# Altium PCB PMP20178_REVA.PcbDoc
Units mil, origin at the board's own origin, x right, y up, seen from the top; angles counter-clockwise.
Board outline 3000 x 2000 mil, 4 copper layers (Top Layer, Mid-Layer 1, Mid-Layer 2, Bottom Layer), stack 61.2 mil thick; 78 components, 25 nets, 160 pads, 125 vias.
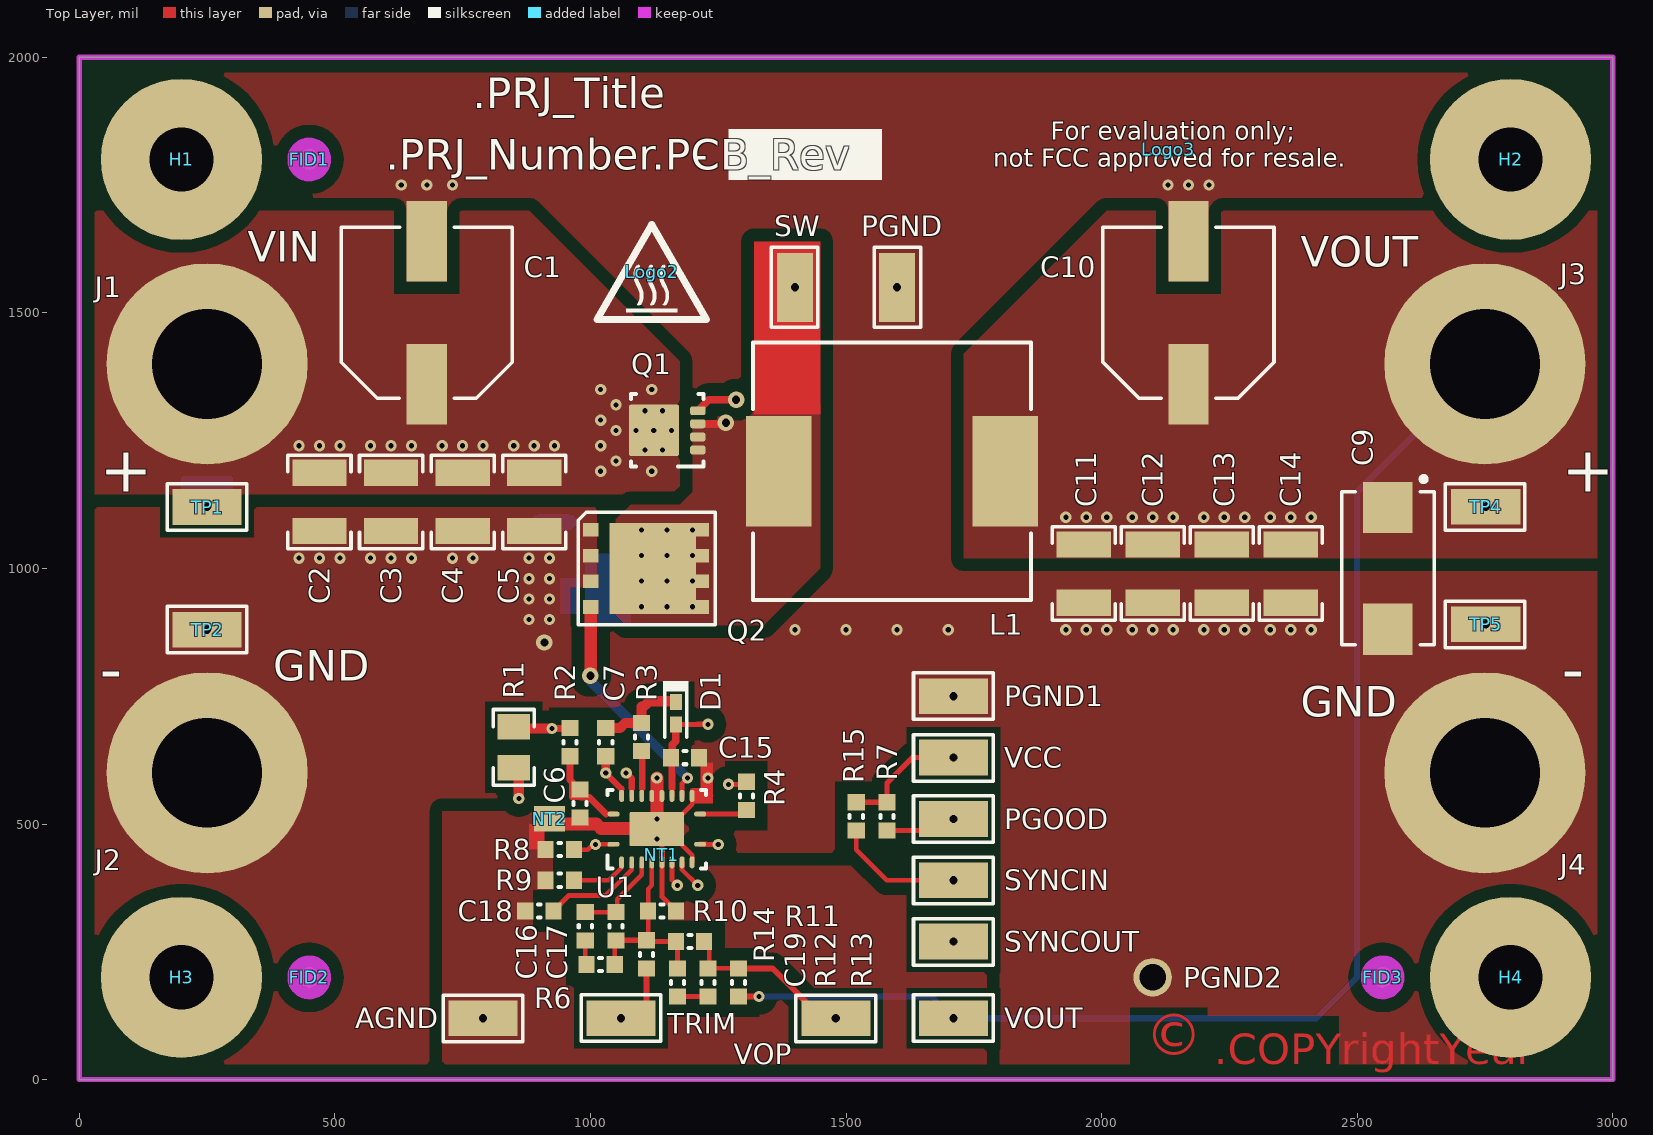
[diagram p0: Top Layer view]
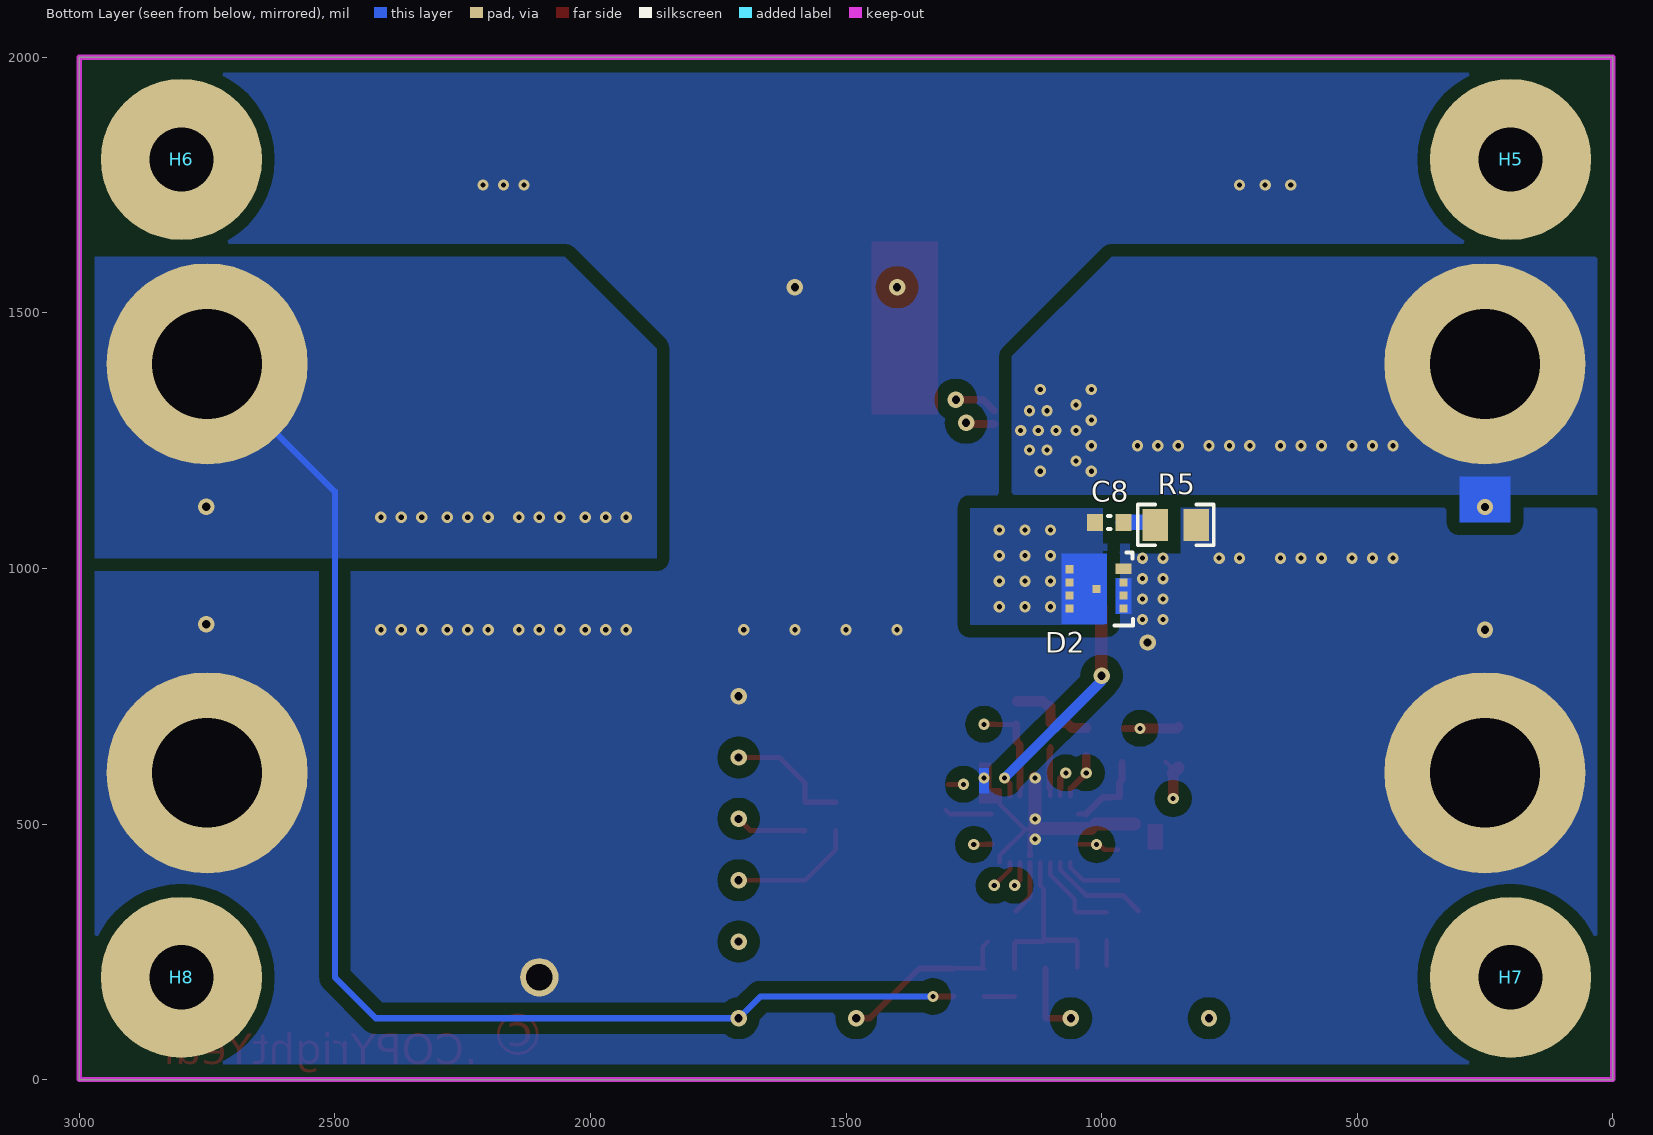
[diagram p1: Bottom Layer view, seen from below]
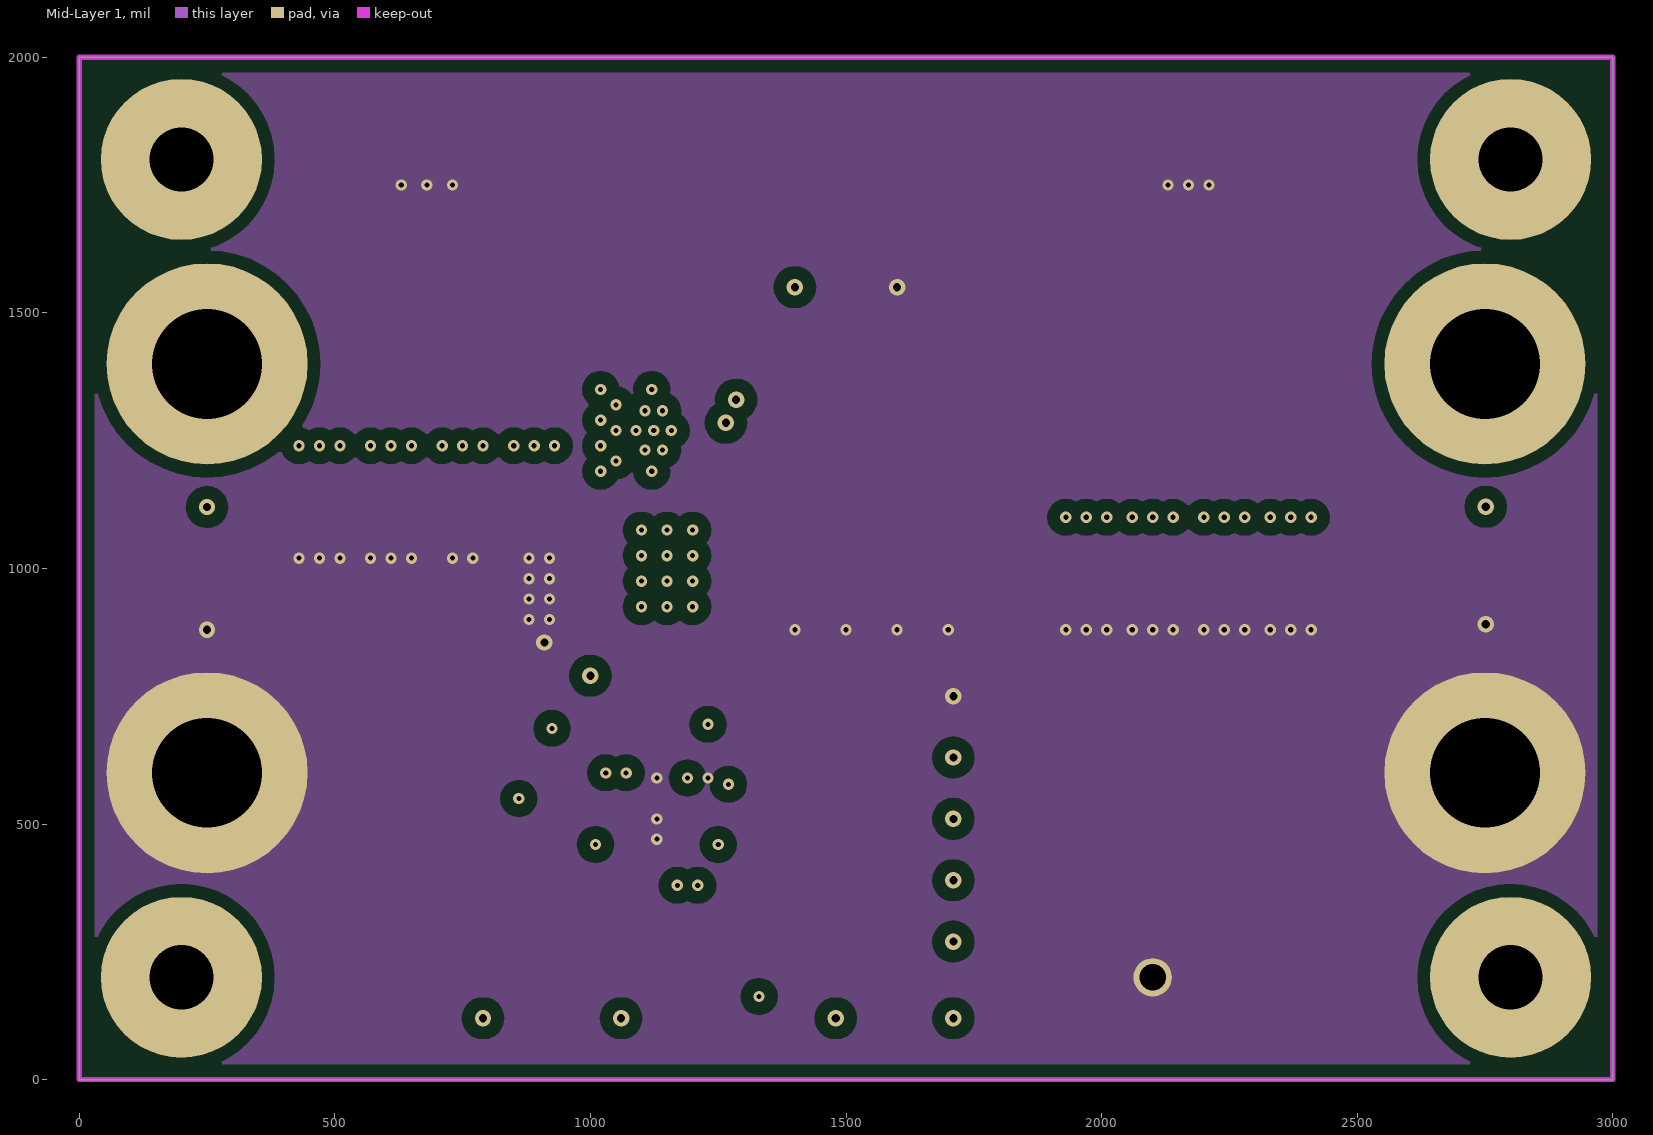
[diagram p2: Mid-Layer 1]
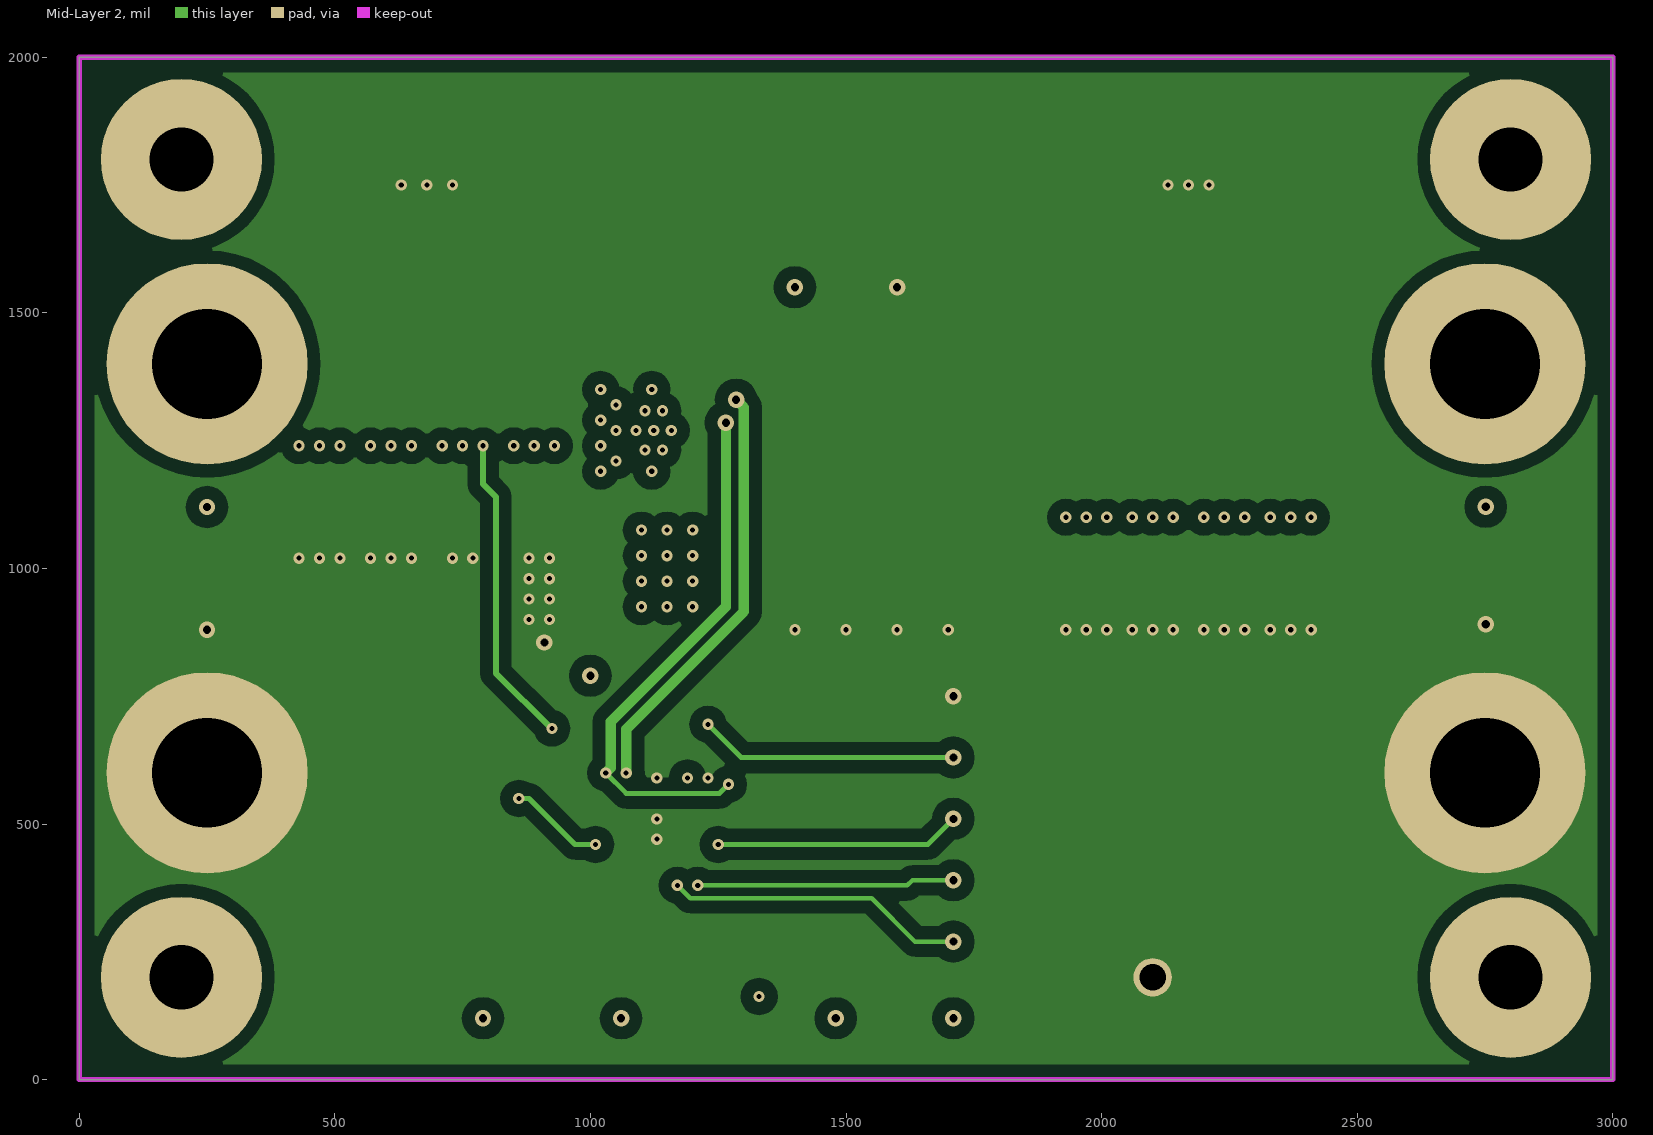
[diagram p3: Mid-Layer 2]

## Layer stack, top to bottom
Top Solder: solder mask 0.4, Solder Resist, Dk 3.5
Top Layer: signal copper 2.8
Dielectric1: prepreg 12, FR-4, Dk 4.2
Mid-Layer 1: signal copper 2.8
Dielectric3: core 26, FR-4, Dk 4.2
Mid-Layer 2: signal copper 2.8
Dielectric2: prepreg 12, FR-4, Dk 4.2
Bottom Layer: signal copper 2.8
Bottom Solder: solder mask 0.4, Solder Resist, Dk 3.5

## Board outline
0,0 3000,0 3000,2000 0,2000

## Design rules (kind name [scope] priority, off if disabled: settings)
AcuteAngle [All] p1: minimum=4.50000000000000E+0001 checktracksonly=FALSE
AssemblyTestPointUsage [All] p1: valid=2
Clearance Clearance_0603 [HasFootprint('0603L') vs HasFootprint('0603L')] p1: gap=20
Clearance Clearance_DQG008A [HasFootprint('DQG0008A') vs HasFootprint('DQG0008A')] p2: gap=8.27
Clearance Clearance_VIN [InNet('VIN')] p3: gap=25
Clearance Clearance_Keepouts [((IsTrack Or IsArc) And Not InPoly) And IsFree and IsKeepOut vs ((IsTrack Or IsArc) And Not InPoly) And IsFree and IsKeepOut] p4: gap=0
Clearance Clearance_BoardEdge_MountingHoles [OnCopper and InComponentClass('Mounting Holes') vs IsKeepOut] p5: gap=37.5
Clearance Clearance_BoardEdge_Poly [OnCopper and InPoly vs IsKeepOut] p6: gap=25
Clearance Clearance_BoardEdge [OnCopper and Not InComponentClass('Logo') and not InComponentClass('FiducialMark') and not InRegion(1000,500,4000,800) and Not IsKeepout vs IsKeepOut] p7: gap=48
Clearance Clearance_Poly [InPolygon] p8: gap=25
Clearance [All] p9: gap=7.87
ComponentClearance ComponentClearance_nETIE10 [HasFootprint('RGY0020B') vs HasFootprint('Net-Tie_10mil')] p1: gap=0 collisioncheckmode=3 verticalgap=0 showdistances=FALSE
ComponentClearance ComponentClearance_nETIE50 [HasFootprint('0603L') vs HasFootprint('Net-Tie_50milWide_30milLong')] p2: gap=0 collisioncheckmode=3 verticalgap=0 showdistances=FALSE
ComponentClearance ComponentClearance_MountingHoles_FiducialMarks [InComponentClass('Mounting Holes') vs InComponentClass('FiducialMark')] p3: gap=50 collisioncheckmode=3 verticalgap=10 showdistances=FALSE
ComponentClearance ComponentClearance_Shunt [InComponentClass('Header') vs InComponentClass('Shunt')] p4: gap=0 collisioncheckmode=3 verticalgap=0 showdistances=FALSE
ComponentClearance ComponentClearance_Logo [InComponentClass('Logo')] p5: gap=50 collisioncheckmode=3 verticalgap=10 showdistances=FALSE
ComponentClearance ComponentClearance_ScrewToNut [(HasFootprint('NY PMS 440 0025 PH')) vs (HasFootprint('Keystone_1902C'))] p6: gap=5 collisioncheckmode=3 verticalgap=10 showdistances=FALSE
ComponentClearance ComponentClearance_MountingHoles [InComponentClass('Mounting Holes')] p7: gap=100 collisioncheckmode=3 verticalgap=100000 showdistances=FALSE
ComponentClearance ComponentClearance_SmallPassives [HasFootprint('0201*') or HasFootprint('0402*') or HasFootprint('0508') or HasFootprint('0603*') or HasFootprint('0612') or HasFootprint('0805*') or HasFootprint('0815*') or HasFootprint('0830*') or HasFootprint('1206*') or HasFootprint('1210*') or HasFootprint('1808*') or HasFootprint('1812*') or HasFootprint('1825*') or HasFootprint('2010*') or HasFootprint('2220*') or HasFootprint('2225*') or HasFootprint('2512*') or HasFootprint('2728*') or HasFootprint('3518*') or HasFootprint('SOD-523') vs HasFootprint('0201*') or HasFootprint('0402*') or HasFootprint('0508') or HasFootprint('0603*') or HasFootprint('0612') or HasFootprint('0805*') or HasFootprint('0815*') or HasFootprint('0830*') or HasFootprint('1206*') or HasFootprint('1210*') or HasFootprint('1808*') or HasFootprint('1812*') or HasFootprint('1825*') or HasFootprint('2010*') or HasFootprint('2220*') or HasFootprint('2225*') or HasFootprint('2512*') or HasFootprint('2728*') or HasFootprint('3518*') or HasFootprint('SOD-523')] p8: gap=20 collisioncheckmode=3 verticalgap=10 showdistances=FALSE
ComponentClearance ComponentClearance_THtoSMT [IsThruComponent vs IsSMTComponent] p9: gap=100 collisioncheckmode=3 verticalgap=30 showdistances=FALSE
ComponentClearance ComponentClearance_THtoTH [IsThruComponent vs IsThruComponent] p10: gap=100 collisioncheckmode=3 verticalgap=30 showdistances=FALSE
ComponentClearance [All] p11: gap=40 collisioncheckmode=3 verticalgap=10 showdistances=FALSE
DiffPairsRouting [All] p1: maxlimit=100 minlimit=10 mostfreqgap=10 toplayer_minwidth=15 toplayer_maxwidth=15 toplayer_prefwidth=15 midlayer1_minwidth=15 midlayer1_maxwidth=15 midlayer1_prefwidth=15 midlayer2_minwidth=15 midlayer2_maxwidth=15 midlayer2_prefwidth=15 bottomlayer_minwidth=15 bottomlayer_maxwidth=15 bottomlayer_prefwidth=15 maxuncoupledlength=1000
FabricationTestPointUsage TestPointUsage [All] p1: valid=2 allowmultiple=FALSE
FabricationTestpoint Testpoint [All] p1: side=3 testpointundercomponent=TRUE minsize=40 maxsize=100 preferedsize=60 minholesize=0 maxholesize=40 preferedholesize=32 testpointgrid=1 allowsidetop=TRUE allowsidebottom=TRUE usegrid=TRUE gridtolerance=0.01
FanoutControl Fanout_LCC [IsLCC] p1: bgadir=Out bgaviamode=Centered fanoutstyle=Auto fanoutdirection=Alternating viagrid=1 // Fanout_LCC (Default Rule)
FanoutControl Fanout_BGA [IsBGA] p2: bgadir=Out bgaviamode=Centered fanoutstyle=Auto fanoutdirection=Alternating viagrid=1 // Fanout_BGA (Default Rule)
FanoutControl Fanout_Default [All] p4: bgadir=Out bgaviamode=Centered fanoutstyle=Auto fanoutdirection=Alternating viagrid=1 // Fanout_Default (Default Rule)
FanoutControl Fanout_Small [(CompPinCount < 5)] p5: bgadir=Out bgaviamode=Centered fanoutstyle=Auto fanoutdirection=OutThenIn viagrid=1 // Fanout_Small (Default Rule)
HoleSize [All] p1: absolutevalues=TRUE maxlimit=251 minlimit=8 maxpercent=80.000 minpercent=20.000
MinimumAnnularRing MinimumAnnularRing_ThermalPadVias [IsVia and InAnyComponent] p1: minimumring=5.91
MinimumAnnularRing [All] p2: minimumring=6
MinimumSolderMaskSliver MinimumSolderMaskSliver_Logo [InComponentClass('Logo') vs InComponentClass('Logo')] p1: minsoldermaskwidth=0.7
MinimumSolderMaskSliver [All] p2: minsoldermaskwidth=3.94
PlaneConnect [All] p1: planeconnectstyle=Direct reliefexpansion=10 reliefentries=4 reliefconductorwidth=10 reliefairgap=10
PolygonConnect [All] p1: connectstyle=Direct reliefconductorwidth=10 reliefentries=4 polygonreliefangle="90 Angle" airgapwidth=10
RoutingVias ThermalPadVias [IsVia and InAnyComponent] p1: holewidth=7.87 width=19.68 viastyle="Through Hole" minholewidth=7.87 minwidth=19.68 maxholewidth=12.99 maxwidth=23.62
RoutingVias [All] p2: holewidth=16 width=34 viastyle="Through Hole" minholewidth=7.87 minwidth=22 maxholewidth=40 maxwidth=65
SilkToBoardRegionClearance [Not ((IsComment or IsDesignator) And (Hide <> 'False')) and not InRegion(1000,500,4000,800)] p1:
SilkToSilkClearance SilkToSilkClearance_Pb-FreeLogo [(HasFootprint('Pb-Free_Overlay_Medium') OR HasFootprint('Pb-Free_Overlay_Small')) vs (HasFootprint('Pb-Free_Overlay_Medium') OR HasFootprint('Pb-Free_Overlay_Small'))] p1: silktosilkclearance=0
SilkToSilkClearance [All] p2: silktosilkclearance=4
SilkToSolderMaskClearance SilkToComonentPadClearance [IsPad and InAnycomponent] p1: minsilkscreentomaskgap=5 clearancetoexposedcopper=TRUE
SilkToSolderMaskClearance "Silk to Solder Mask Opening" [All] p2: minsilkscreentomaskgap=4 clearancetoexposedcopper=FALSE
SolderMaskExpansion [All] p1: expansion=1.97
UnpouredPolygon [All] p1: allowunpoured=FALSE
Width [All] p1: maxlimit=100 minlimit=6 preferedwidth=10 checkconnectedcopper=TRUE
14 further rules are at their usual default settings.

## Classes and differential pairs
component class AssemblyNote: ZZ2 ZZ3 ZZ4
component class FiducialMark: FID1 FID2 FID3
component class PMP20178_REVA_Sh2: FID1 FID2 FID3 H1 H2 H3 H4 H5 H6 H7 H8 Logo2 Logo3 ZZ2 ZZ3 ZZ4
component class "Mounting Holes": H1 H2 H3 H4

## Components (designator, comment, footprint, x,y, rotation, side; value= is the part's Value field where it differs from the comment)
AGND "5015" Testpoint_Keystone_Miniature#1 790,120 r0 top
C1 "EEE-FK2A220P" SM_RADIAL_F 680,1500 r90 top
C2 "C3225X7S2A475K200AB" 1210 470,1130 r270 top
C3 "C3225X7S2A475K200AB" 1210 610,1130 r270 top
C4 "C3225X7S2A475K200AB" 1210 750,1130 r270 top
C5 "C3225X7S2A475K200AB" 1210 890,1130 r270 top
C6 "GRM188R72A104KA35D" 0603L 980,540 r270 top
C7 "GRM188R72A104KA35D" 0603L 1030,660 r90 top
C8 "C1608C0G2A101F080AA" 0603L 985,1090 r180 bottom
C9 "6TPE470MAZU" 7343-20 2560,1000 r270 top
C10 "DNP" SM_RADIAL_F 2170,1500 r90 top
C11 "GRM32ER71A476KE15L" 1210_270 1965,990 r270 top
C12 "GRM32ER71A476KE15L" 1210_270 2100,990 r270 top
C13 "GRM32ER71A476KE15L" 1210_270 2235,990 r270 top
C14 "GRM32ER71A476KE15L" 1210_270 2370,990 r270 top
C15 "C1608X7R1E105K080AB" 0603L 1185,629.69 r0 top
C16 "GRM188R71H472KA01D" 0603L 990,300 r270 top
C17 "GRM1885C1H470JA01D" 0603L 1050,300 r270 top
C18 "C1608X7R1H473K080AA" 0603L 900,330 r180 top
C19 "GRM188R71H332KA01D" 0603L 1170,190 r90 top
D1 "BAS516,115" SOD-523 1167.21,716.63 r270 top
D2 "STPS6M100DEE-TR" PowerFLAT_3_3x3_3 1010,960 r0 bottom
FID1 "Fiducial" Fiducial10-20 450,1800 r0 top
FID2 "Fiducial" Fiducial10-20 450,200 r0 top
FID3 "Fiducial" Fiducial10-20 2550,200 r0 top
H1 "NY PMS 440 0025 PH" "NY PMS 440 0025 PH" 200,1800 r0 top
H2 "NY PMS 440 0025 PH" "NY PMS 440 0025 PH" 2800,1800 r0 top
H3 "NY PMS 440 0025 PH" "NY PMS 440 0025 PH" 200,200 r0 top
H4 "NY PMS 440 0025 PH" "NY PMS 440 0025 PH" 2800,200 r0 top
H5 "1902C" Keystone_1902C 200,1800 r180 bottom locked
H6 "1902C" Keystone_1902C 2800,1800 r180 bottom locked
H7 "1902C" Keystone_1902C 200,200 r180 bottom locked
H8 "1902C" Keystone_1902C 2800,200 r180 bottom locked
J1 "VIN" Keystone575-8 250,1400 r0 top
J2 "GND" Keystone575-8 250,600 r0 top
J3 "VOUT" Keystone575-8 2750,1400 r0 top
J4 "GND" Keystone575-8 2750,600 r0 top
L1 "CMLB135T3R3MSS" CMLB136T 1590,1190 r0 top
Logo2 "CAUTION HOT SURFACE" IEC_HotSurface_Small 1120,1580 r0 top
Logo3 "FCC disclaimer" FCC_disclaimer_stacked 2130,1820 r0 top
NT1 "Net-Tie" Net-Tie_10mil 1140,440 r270 top net-tie
NT2 "Net-Tie" Net-Tie_50milWide_30milLong 920,510 r180 top net-tie
PGND "5015" Testpoint_Keystone_Miniature#1 1600,1550 r90 top
PGND1 "5015" Testpoint_Keystone_Miniature#1 1710,750 r180 top
PGND2 "1040" CONN_1040 2100,200 r180 top
PGOOD "5015" Testpoint_Keystone_Miniature#1 1710,510 r0 top
Q1 "CSD19537Q3" DQG0008A 1150,1270 r180 top
Q2 "CSD19533Q5A" TRANS_NexFET_Q5A 1110,1000 r0 top
R1 "CRCW0805499KFKEA" 0805_HV 850,650 r90 top
R2 "CRCW06032R20JNEA" 0603L 960,660 r90 top
R3 "CRCW06030000Z0EA" 0603L 1100,670 r90 top
R4 "CRCW0603523RFKEA" 0603L 1305,555 r90 top
R5 "RC0805FR-072R2L" 0805_HV 855,1085 r0 bottom
R6 "CRCW06036K80JNEA" 0603L 1020,225 r180 top
R7 "CRCW060320K0FKEA" 0603L 1580,515 r270 top
R8 "CRCW060312K4FKEA" 0603L 940,450 r0 top
R9 "CRCW060328K7FKEA" 0603L 940,390 r0 top
R10 "CRCW06033K83FKEA" 0603L 1140,330 r180 top
R11 "CRCW060320K0FKEA" 0603L 1195,270 r0 top
R12 "CRCW06033K60JNEA" 0603L 1230,190 r90 top
R13 "CRCW060310R0FKEAHP" 0603L 1290,190 r270 top
R14 "CRCW060310K0FKEA" 0603L 1110,245 r90 top
R15 "CRCW060320K0FKEA" 0603L 1520,515 r270 top
SW "5015" Testpoint_Keystone_Miniature#1 1400,1550 r270 top
SYNCIN "5015" Testpoint_Keystone_Miniature#1 1710,390 r0 top
SYNCOUT "5015" Testpoint_Keystone_Miniature#1 1710,270 r0 top
TP1 "5015" Testpoint_Keystone_Miniature#1 250,1120 r180 top
TP2 "5015" Testpoint_Keystone_Miniature#1 250,880 r180 top
TP4 "5015" Testpoint_Keystone_Miniature#2 2750,1120 r180 top
TP5 "5015" Testpoint_Keystone_Miniature#2 2750,890 r180 top
TRIM "5015" Testpoint_Keystone_Miniature#1 1060,120 r180 top
U1 "LM5145RGYR" RGY0020B 1130,490 r90 top
VCC "5015" Testpoint_Keystone_Miniature#1 1710,630 r0 top
VOP "5015" Testpoint_Keystone_Miniature#1 1480,120 r0 top
VOUT "5015" Testpoint_Keystone_Miniature#1 1710,120 r180 top
ZZ2 "These assemblies are ESD sensitive, ESD precautions shall be observed." AssemblyNote 185,3829.11 r0 top
ZZ3 "These assemblies must be clean and free from flux and all contaminants. Use of no clean flux is not acceptable." AssemblyNote 185,3740.56 r0 top
ZZ4 "These assemblies must comply with workmanship standards IPC-A-610 Class 2, unless otherwise specified." AssemblyNote 185,3652 r0 top

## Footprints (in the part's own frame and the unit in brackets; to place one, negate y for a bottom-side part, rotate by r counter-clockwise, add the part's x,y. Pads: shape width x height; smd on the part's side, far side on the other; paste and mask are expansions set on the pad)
0603L [mm] "0603 from SM-752 data"
  rect 0.8x0.85 smd: 1(-0.7,0) 2(0.7,0)
  silkscreen extent -0.07,-0.33 0.07,0.33, body extent -0.87,-0.47 0.87,0.47, height 1
0805_HV [mil] "0805 with 30mil clearance between pads"
  rect 50x63 smd: 1(-40,0) 2(40,0)
  silkscreen extent -74,-40 74,40, body extent -43,-29 43,29, height 57
1210 [mm] "1210 from SM-752 data"
  rect 1.3x2.7 smd: 1(-1.45,0) 2(1.45,0)
  silkscreen extent -2.32,-1.57 2.32,1.57, body extent -1.7,-1.35 1.7,1.35, height 1.35
1210_270 [mm] "1210"
  rect 1.3x2.7 smd: 1(-1.45,0) 2(1.45,0)
  silkscreen extent -2.32,-1.57 2.32,1.57, body extent -1.7,-1.35 1.7,1.35, height 2.7
7343-20 [mm] "Medium density IPC, based on Kemet case V from T495 datasheet"
  rect 2.55x2.45 smd: 1(-3.025,0) 2(3.025,0)
  silkscreen extent -4.56,-2.3 3.8,2.3, body extent -3.8,-2.3 3.8,2.3, height 2
AssemblyNote [mil] "Assembly Note"
CMLB136T [mm] "SMD, 2-Leads, Body 13.45x12.6mm"
  rect 3.25x5.5 smd: 1(-5.625,0) 2(5.625,0)
  silkscreen extent -6.9,-6.4 6.9,6.4, body extent -6.9,-6.4 6.9,6.4, height 6
CONN_1040 [mil] "Test Point, PC  test point Terminal"
  round 75 hole 52: 1(0,0)
  body extent -55,-12 55,13, height 276
DQG0008A [mm] "SMD, 8-Leads, Body 3.3x3.3mm, Pitch 0.65mm"
  rrect45% 0.75x0.44 smd paste-0.05 mask-0.05: 1(-1.525,0.975) 2(-1.525,0.325) 3(-1.525,-0.325) 4(-1.525,-0.975) 5(1.525,-0.975) 6(1.525,-0.325) 7(1.525,0.325) 8(1.525,0.975)
  rrect15% 0.676x1.125 on Top Paste: 9(-0.212,0.662) 9(-0.212,-0.663) 9(0.664,0.662) 9(0.664,-0.663)
  rrect6% 1.775x2.45 on Top Solder: 9(0.327,0)
  rrect8% 2.5x2.55 smd paste-1.5 mask-1.5: 9(0.65,0)
  rrect29% 0.5x0.34 on Top Solder: 9(1.175,0.975) 9(1.175,-0.325) 9(1.175,0.325) 9(1.175,-0.975)
  silkscreen extent -1.8,-1.8 1.8,1.8, body extent -1.65,-1.65 1.65,1.65, height 1.1
FCC_disclaimer_stacked [mil]
Fiducial10-20 [mm]
  round 1 smd mask+0.5: 1(0,0)
  Top Layer keep-out circle w1.178: c0,0 r0.5
IEC_HotSurface_Small [mil]
  silkscreen extent -107,-93 107,92
Keystone575-8 [mm] "Banana Jack"
  round 10 hole 5.45: 1(0,0)
  body extent -3.92,-3.94 3.95,3.94, height 2.36
Keystone_1902C [mil] "Hex Standoff, 4-40 threaded, nylon"
  body extent -145,-126 146,126, height 501
Net-Tie_10mil [mil] "10mil net tie, no solder mask opening, no solder paste"
  rect 10x10 smd paste-5 mask-5: 1(-10,0) 2(10,0)
  Top Layer region: -6,5 6,5 6,-5 -6,-5
Net-Tie_50milWide_30milLong [mil] "50mil net tie, no solder mask opening, no solder paste"
  rect 30x50 smd paste-20 mask-20: 1(-15,0) 2(15,0)
"NY PMS 440 0025 PH" [mm] "4-40 nylon screw and mounting hole"
  round 8 hole 3.2: 1(0,0)
  body extent -3.3,-3.3 3.3,3.3, height 2.69
PowerFLAT_3_3x3_3 [mm] "SMD, 8-Leads, Body 3.3x3.3mm"
  rect 0.4x0.4 smd: 1(-1.35,0.975) 2(-1.35,0.325) 3(-1.35,-0.325) 5(1.35,-0.975) 6(1.35,-0.325) 7(1.35,0.325) 8(1.35,0.975) 9(0,0)
  rect 0.8x0.52 smd: 4(-1.35,-1.01)
  Top Layer region: -0.53,1.75 1.75,1.75 1.75,-1.75 -0.53,-1.75
  Top Layer region: -1.75,1.25 -0.95,1.25 -0.95,-0.54 -1.75,-0.54
  silkscreen extent -1.83,-1.8 -0.9,1.83, body extent -1.7,-1.7 1.7,1.7, height 1.06
RGY0020B [mm] "QFN, 20-Leads, Body 4.5x3.5mm, Pitch 0.5mm, Thermal Pad 2.7x1.7mm"
  rrect100% 0.24x0.6 smd: 1(-0.75,2.15) 10(-0.75,-2.15) 11(0.75,-2.15) 20(0.75,2.15)
  rrect100% 0.6x0.24 smd: 2(-1.65,1.75) 3(-1.65,1.25) 4(-1.65,0.75) 5(-1.65,0.25) 6(-1.65,-0.25) 7(-1.65,-0.75) 8(-1.65,-1.25) 9(-1.65,-1.75) 12(1.65,-1.75) 13(1.65,-1.25) 14(1.65,-0.75) 15(1.65,-0.25) 16(1.65,0.25) 17(1.65,0.75) 18(1.65,1.25) 19(1.65,1.75)
  rrect6% 1.7x2.7 smd paste-1.4: 21(0,0)
  silkscreen extent -1.95,-2.45 1.95,2.45, body extent -1.75,-2.25 1.75,2.25, height 0.9
SM_RADIAL_F [mm] "8 x 10.2mm:  Panasonic F"
  rect 4x2 smd: 1(-3.55,0) 2(3.55,0)
  silkscreen extent -4.25,-4.25 4.25,4.25, body extent -4.26,-4.26 4.26,4.26, height 10.5
SOD-523 [mm] "NXP Semiconductor recommended land pattern, nominal STEP model"
  rect 0.8x0.6 smd paste-0.05: 1(-0.55,0) 2(0.55,0)
  silkscreen extent -1.6,-0.64 1.2,0.63, body extent -0.8,-0.4 0.8,0.4, height 0.72
Testpoint_Keystone_Miniature#1 [mil] "Miniature SMT test point"
  rect 135x70 smd: 1(0,0)
  silkscreen extent -78,-46 78,45, body extent -52,-20 52,20, height 61
Testpoint_Keystone_Miniature#2 [mil] "Miniature SMT test point"
  rect 135x70 smd: 1(-1.51,-0.67)
  silkscreen extent -78,-46 78,45, body extent -52,-20 52,20, height 61
TRANS_NexFET_Q5A [mm] "TI recommended land pattern (nominal) M0139-01"
  rect 0.75x0.675 smd paste-0.1 mask+0.051: 1(-2.776,1.917) 2(-2.776,0.639) 3(-2.776,-0.639) 4(-2.776,-1.917)
  rect 0.655x0.675 smd paste-0.1 mask+0.051: 5(2.776,-1.917) 6(2.776,-0.639) 7(2.776,0.639) 8(2.776,1.917)
  rect 4.295x4.51 smd paste-2.2 mask+0.051: 9(0.301,0)
  silkscreen extent -3.4,-2.8 3.4,2.8, body extent -3.05,-2.5 3.05,2.5, height 1.11

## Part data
AGND PGND PGND1 PGOOD SW SYNCIN SYNCOUT TP1 TP2 TP4 TP5 TRIM VCC VOP VOUT: "Test Point, Miniature, SMT"
C1: "CAP, AL, 22 µF, 100 V, +/- 20%, 1.3 ohm, SMD"
C2 C3 C4 C5: "CAP, CERM, 4.7 µF, 100 V, +/- 10%, X7S, 1210"
C6 C7: "CAP, CERM, 0.1 µF, 100 V, +/- 10%, X7R, 0603"
C8: "CAP, CERM, 100 pF, 100 V, +/- 1%, C0G/NP0, 0603"
C9: "CAP, Tantalum Polymer, 470 µF, 6.3 V, +/- 20%, 0.035 ohm, 7343-20 SMD"
C10: library part EEE-FK1A471P, "CAP, AL, 470 µF, 10 V, +/- 20%, 0.16 ohm, SMD"
C11 C12 C13 C14: "CAP, CERM, 47 µF, 10 V, +/- 10%, X7R, 1210"
C15: "CAP, CERM, 1 µF, 25 V, +/- 10%, X7R, 0603"
C16: "CAP, CERM, 4700 pF, 50 V, +/- 10%, X7R, 0603"
C17: "CAP, CERM, 47 pF, 50 V, +/- 5%, C0G/NP0, 0603"
C18: "CAP, CERM, 0.047 µF, 50 V, +/- 10%, X7R, 0603"
C19: "CAP, CERM, 3300 pF, 50 V, +/- 10%, X7R, 0603"
D1: "Diode, Switching, 100 V, 0.25 A, SOD-523"
D2: "Diode, Schottky, 100 V, 6 A, 8-PowerTDFN"
FID1 FID2 FID3: "Fiducial mark.  There is nothing to buy or mount."
H1 H2 H3 H4: "Machine Screw, Round, #4-40 x 1/4, Nylon, Philips panhead"
H5 H6 H7 H8: "Standoff, Hex, 0.5\"L #4-40 Nylon"
J1 J2 J3 J4: library part 575-8, "Standard Banana Jack, Uninsulated, 8.9mm"
L1: library part CMLB136T-220MS, "Inductor, 3.3 µH, 14 A, 0.010 ohm, SMD"
Logo2: library part IEC_HotSurface, "IEC 61010-1 Hot Surface Warning"
Logo3: library part FCC_disclaimer, "FCC_disclaimer"
NT1 NT2: "Single point connection between nets."
PGND2: "TEST POINT SLOTTED .118\", TH"
Q1: "MOSFET, N-CH, 100 V, 50 A, VSON-CLIP-8"
Q2: "MOSFET, N-CH, 100 V, 13 A, SON 5x6mm"
R1: "RES, 499 k, 1%, 0.125 W, 0805"
R2: "RES, 2.2, 5%, 0.1 W, 0603"
R3: "RES, 0, 5%, 0.1 W, 0603"
R4: "RES, 523, 1%, 0.1 W, 0603"
R5: "RES, 2.20, 1%, 0.125 W, 0805"
R6: "RES, 6.8 k, 5%, 0.1 W, 0603"
R7 R11 R15: "RES, 20.0 k, 1%, 0.1 W, 0603"
R8: "RES, 12.4 k, 1%, 0.1 W, 0603"
R9: "RES, 28.7 k, 1%, 0.1 W, 0603"
R10: "RES, 3.83 k, 1%, 0.1 W, 0603"
R12: "RES, 3.6 k, 5%, 0.1 W, 0603"
R13: "RES, 10.0, 1%, 0.25 W, 0603"
R14: "RES, 10.0 k, 1%, 0.1 W, 0603"
U1: "Wide Input Range Synchronous Buck Controller, RGY0020B"
ZZ2 ZZ3 ZZ4: library part AssemblyNote

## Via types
v1: diameter 22, hole 10, Top Layer to Bottom Layer, tented both sides, 77 vias
v2: diameter 22, hole 10, Top Layer to Bottom Layer, 29 vias
v3: diameter 32, hole 16, Top Layer to Bottom Layer, 18 vias
v4: diameter 32, hole 16, Top Layer to Bottom Layer, tented both sides, 1 vias

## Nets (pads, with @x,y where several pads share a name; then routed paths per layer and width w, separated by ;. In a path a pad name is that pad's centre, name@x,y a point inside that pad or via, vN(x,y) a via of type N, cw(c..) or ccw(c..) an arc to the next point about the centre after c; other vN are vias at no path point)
AGND: AGND.1 C18.2 NT1.2 NT2.2 R8.1 R9.1 R10.1 U1.6 | length 106.5
  Top Layer w10: U1.6 1139.84,357.72 R10.1
  other v3: 790,120
BST: R3.1 U1.17 | length 94.6
  Top Layer w9: R3.1@1100,652.44 R3.1@1100.47,651.97
  Top Layer w9.4: U1.17 1100.47,570.17 1101.16,570.86
  Top Layer w13: R3.1@1100,647.44 1101.16,646.28 1101.16,570.86 1101.16,570.17
COMP: C16.1 C17.1 U1.4 | length 174.4
  Top Layer w9: C16.1 C17.1 ; C17.1@1052.8,330.36 1052.8,352.8 1100.47,400.47 U1.4
EN: R1.1 R8.2 U1.1 | length 349.9
  Top Layer w9: R1.1@860,606.54 R1.1@875,621.54 ; R8.2 994.62,450 v1@1005.09,460.47 ; v1@1010,460.47 U1.1
  Top Layer w20: v1(860,550) R1.1@860,600
  Top Layer w25: R1.1 R1.1@860,600
  Mid-Layer 2 w10: v1(860,550) 880,550 970,460 v1(1010,460)
FB: C17.2 C19.2 R6.1 R10.2 R11.1 R14.2 U1.5 | length 375
  Top Layer w9: R6.1@1047.56,220 C17.2@1047.56,270.01 ; R14.2 1112.8,275.35 1112.8,372.8 1120.16,380.16 U1.5
  Top Layer w10: C17.2@1050.11,272.56 R14.2 ; R14.2@1112.56,270 R11.1 1170,267.44 C19.2
HO: Q1.4 U1.18 | length 964.9
  Top Layer w9.4: U1.18 1080.79,569.39
  Top Layer w12: v1(1070,600) 1080.79,589.21 1080.79,569.39
  Top Layer w15: Q1.4 1231.65,1330 v3(1285,1330)
  Mid-Layer 2 w20: v1(1070,600) 1070,685.58 1300,915.58 1300,1315 v3(1285,1330)
ILIM: R4.1 U1.11 | length 93.6
  Top Layer w9: U1.11 1297.09,519.53 R4.1
LO: Q2.4 U1.13 | length 458
  Top Layer w9.4: U1.13 1179.21,566.35 U1.13@1179.45,566.59
  Top Layer w10: U1.13@1179.45,566.59 1179.45,579.45 v1(1190,590) v1@1185,590
  Top Layer w25: v3(1000,790) 1000.7,790.7 Q2.4
  Bottom Layer w20: v3(1000,790) 1000,780 v1(1190,590)
NetC7_2: C7.2 D1.1 R3.2 | length 178.3
  Top Layer w20: C7.2 1057.56,687.56 1067.56,697.56 R3.2 1100,725 ; 1100,730 1100,725 ; D1.1@1165.49,740 1115,740 1100,725
NetC8_2: C8.2 R5.2 | length 64.5
  Bottom Layer w30: R5.2 900,1090 C8.2
NetC16_2: C16.2 R6.2 | length 50
  Top Layer w9: R6.2@990,222.44 C16.2
NetC19_1: C19.1 R12.1 | length 60
  Top Layer w10: C19.1 R12.1
NetR14_1: R14.1 TRIM.1 | length 147.4
  Top Layer w12: v3(1060,120) 1110,120 R14.1
PGND: C1.2 C2.2 C3.2 C4.2 C5.2 C6.2 C9.2 C10.2 C11.2 C12.2 C13.2 C14.2 C15.2 D2.1 D2.2 D2.3 D2.4 J2.1 J4.1 NT1.1 NT2.1 PGND1.1 PGND2.1 PGND.1 Q2.1 Q2.2 Q2.3 R5.1 TP2.1 TP5.1 U1.9 U1.12 U1.15 U1.16 U1.21 | length 545.5
  Top Layer w9: NT1.1 1140,480 U1.21 U1.21@1147.8,490 ; U1.9 1198.9,438.9 U1.21@1147.8,490 ; U1.12@1198.9,565.84 U1.12 1198.9,538.9 1150,490 U1.21@1147.8,490
  Top Layer w25: NT2.1@935,500 1011.99,500 1020.55,491.45 1128.55,491.45 U1.21 v2(1130,509.68) v1(1130,590)
  other v1: 1230,590 1400,880 1500,880 1600,880 1700,880 1930,880 1970,880 2010,880 2060,880 2100,880 2140,880 2200,880 2240,880 2280,880 2330,880 2370,880 2410,880 880,900 920,900 880,940 920,940 880,980 920,980 430,1020 470,1020 510,1020 570,1020 610,1020 650,1020 730,1020 770,1020 880,1020 920,1020 630,1750 680,1750 730,1750 2130,1750 2170,1750 2210,1750
  other v2: 1130,470.32
  other v3: 1710,750 910,855 250,880 2751.51,890.67
  other v4: 1600,1550
PGOOD: PGOOD.1 R7.2 U1.10 | length 659.1
  Top Layer w10: U1.10 1225.92,460.47 1226.39,460 v1(1250,460) ; R7.2@1582.44,485 R7.2 1687.44,487.44 v3(1710,510)
  Mid-Layer 2 w10: v1(1250,460) 1660,460 v3(1710,510)
RT: R9.2 U1.2 | length 114
  Top Layer w9: R9.2 1036.14,390 1061.1,414.97 U1.2
SS: C18.1 U1.3 | length 200.9
  Top Layer w9: 1040,370 1080.79,410.79 U1.3
  Top Layer w10: C18.1 957.56,360 1030,360 1040,370
SW: C7.1 C8.1 D2.5 D2.6 D2.7 D2.8 D2.9 L1.1 Q1.1 Q1.2 Q1.3 Q2.5 Q2.6 Q2.7 Q2.8 Q2.9 R4.2 SW.1 U1.19 | length 1222.7
  Top Layer w9.4: U1.19 1061.1,568.9
  Top Layer w10: v1(1270,577.57) R4.2@1300.01,577.57
  Top Layer w12: v1(1030,600) 1030,599.17 1060.27,568.9 1060.91,568.9
  Top Layer w15: v3@1262.8,1282.8 v3(1265,1285)
  Top Layer w16: v1(1030,600) C7.1 ; Q1.3 v3@1262.8,1282.8
  Mid-Layer 2 w10: v1(1030,600) 1070,560 1252.43,560 v1(1270,577.57)
  Mid-Layer 2 w20: v1(1030,600) 1040,610 1040,700 1265,925 v3(1265,1285)
  other v2: 1100,925 1150,925 1200,925 1100,975 1150,975 1200,975 1100,1025 1150,1025 1200,1025 1100,1075 1150,1075 1200,1075
  other v3: 1400,1550
SYNCIN: R15.2 SYNCIN.1 U1.8 | length 814.2
  Top Layer w9: U1.8 1179.21,410.79 v1(1210,380) ; R15.2 1520,450 1580,390 1610,390 v3(1710,390)
  Mid-Layer 2 w9: v1(1210,380) 1620,380 1630,390 v3(1710,390)
SYNCOUT: SYNCOUT.1 U1.7 | length 634.9
  Top Layer w9: U1.7 1159.53,390.47 v1(1170,380)
  Mid-Layer 2 w9: v1(1170,380) 1195,355 1550,355 1635,270 v3(1710,270)
VCC: C15.1 D1.2 R7.1 R15.1 U1.14 VCC.1 | length 961.2
  Top Layer w9.4: U1.14 1159.53,569.53
  Top Layer w10: D1.2 1210,695.22 1229.78,695.22 v1(1230,695) ; R15.1 R7.1 1580,580 1630,630 v3(1710,630)
  Top Layer w12: C15.1@1159.53,626.66 C15.1@1160,627.13
  Top Layer w13: 1159.53,569.53 C15.1@1159.53,626.66
  Top Layer w15: C15.1@1160,627.13 1160,655 1167.21,662.21 D1.2
  Mid-Layer 2 w10: v1(1230,695) 1295,630 v3(1710,630)
VIN: C1.1 C2.1 C3.1 C4.1 C5.1 J1.1 Q1.5 Q1.6 Q1.7 Q1.8 Q1.9@1124.41,1270 R1.2 R2.2 TP1.1 | length 716.9
  Top Layer w14: v1(925,687.02) R2.2@955.54,687.02
  Top Layer w20: R1.2 852.98,687.02 v1(925,687.02)
  Mid-Layer 2 w12: v1(790,1240) 790,1165 815,1140 815,795 922.98,687.02 v1(925,687.02)
  other v1: 430,1240 470,1240 510,1240 570,1240 610,1240 650,1240 710,1240 750,1240 850,1240 890,1240 930,1240 1089.37,1270
  other v2: 1020,1190 1120,1190 1050,1210 1106.61,1231.61 1141.1,1231.61 1020,1240 1050,1270 1123.86,1270 1158.35,1270 1020,1290 1106.61,1308.39 1141.1,1308.39 1050,1320 1020,1350 1120,1350
  other v3: 250,1120
VINC: C6.1 R2.1 U1.20 | length 163.5
  Top Layer w9.4: 1030.47,519.53 U1.20
  Top Layer w12: C6.1@965,552.56 975,552.56 C6.1@981.22,552.56
  Top Layer w13: C6.1@981.22,552.56 997.44,552.56 1030.47,519.53
  Top Layer w14: R2.1@960,620 960,586 965,581 C6.1@965,552.56
VOP: R11.2 R12.2 R13.1 VOP.1 | length 344.5
  Top Layer w9: R11.2 1232.44,260.12 R12.2@1232.44,220 ; R12.2 R13.1
  Top Layer w12: R13.1 1356.22,217.56 1453.78,120 v3(1480,120)
VOUT: C9.1 C10.1 C11.1 C12.1 C13.1 C14.1 J3.1 L1.2 R13.2 TP4.1 VOUT.1 | length 2564.3
  Top Layer w12: R13.2 v1(1330,162.44)
  Bottom Layer w12: v1(1330,162.44) 1667.56,162.44 v3(1710,120) 2420,120 2500,200 2500,1150 J3.1
  other v1: 1930,1100 1970,1100 2010,1100 2060,1100 2100,1100 2140,1100 2200,1100 2240,1100 2280,1100 2330,1100 2370,1100 2410,1100
  other v3: 2751.51,1120.67
pads on no net: FID1.1 FID2.1 FID3.1 H1.1 H2.1 H3.1 H4.1 Q1.9@1103.74,1231.61 Q1.9@1103.74,1257.2 Q1.9@1103.74,1282.8 Q1.9@1103.74,1308.39 Q1.9@1123.86,1243.92 Q1.9@1123.86,1296.08 Q1.9@1137.11,1270 Q1.9@1158.35,1243.92 Q1.9@1158.35,1296.08

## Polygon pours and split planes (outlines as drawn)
PGND on Top Layer "Top Layer-PGND" (solid, remove dead copper, pour order 18): -3.39,-0.45 3000,-0.45 3000,1999.55 -3.39,1999.55
VOUT on Top Layer "Top Layer-VOUT" (solid, pour order 17): 3000,1700 2010,1700 1730,1420 1730,1020 3000,1020
SW on Top Layer "Top Layer-SW" (solid, pour order 14): 1450,1317.97 1450,1000 1339.29,889.29 1069.13,889.29 1050,908.43 1050,1096.3 1078.7,1125 1175,1125 1200,1150 1200,1360.75 1407.23,1360.75
VIN on Top Layer "Top Layer-VIN" (solid, pour order 16): 1175,1145 0,1145 0,1700 880,1700 1175,1405
AGND on Top Layer "Top Layer-AGND" (solid, pour order 15): 1775.49,418.15 1775.49,0 710,0 710,525 980,525 980,418.15
VOUT on Bottom Layer "Bottom Layer-VOUT" (solid, pour order 13): 2050,1610 3000,1610 3000,1020 1870,1020 1870,1430
VIN on Bottom Layer "Bottom Layer-VIN" (solid, pour order 22): 1175.29,1144.24 0.29,1144.24 0.29,1610 980,1610 1175.29,1414.71
PGND on Bottom Layer "Bottom Layer-PGND" (solid, remove dead copper, pour order 23): 0,0 3000,0 3000,2000 0,2000
SW on Bottom Layer "Bottom Layer-SW" (solid, pour order 21): 988.94,1118.11 1257.24,1118.11 1257.24,890 988.94,890
PGND on Mid-Layer 1 "Mid-Layer1-PGND" (solid, remove dead copper, pour order 19): 0,0 3000,0 3000,2000 0,2000
PGND on Mid-Layer 2 "Mid-Layer2-PGND" (solid, remove dead copper, pour order 20): 0,0 3000,0 3000,2000 0,2000

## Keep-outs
Keep-Out Layer:
  the board outline again, w10
  text ".Layer_Name" at 577,-858.49 h60

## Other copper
Top Layer:
  rectangle net AGND: 880,450 910,500
  rectangle net SW: 1320,1300.76 1450,1640
  rectangle net PGND: 1200,540 1220,570
  rectangle net PGND: 1215,540 1240,620
  text ".COPYrightYear" at 2220,30 h60
  text "©" at 2085,20 h140
  text ".Layer_Name" at 577,-858.49 h60
Bottom Layer:
  rectangle net VIN: 200,1090 300,1180
  rectangle net PGND: 1220,560 1240,610
  text ".Layer_Name" at 577,-858.49 h60

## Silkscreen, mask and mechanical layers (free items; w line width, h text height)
Top Overlay:
  region: 1570,1860 1270,1860 1270,1760 1570,1760
  text ".PRJ_Title" at 770,1900 h60
  text ".PRJ_Number" at 600,1780 h60
  text ".PCB_Rev" at 1120,1780 h60
  text "-" at 1200,1780 h60
  text "+" at 40,1150 h90
  text "+" at 2900,1150 h90
  text "-" at 40,760 h90
  text "-" at 2900,760 h90
  text ".Layer_Name" at 577,-858.49 h60
Bottom Overlay:
  text ".Layer_Name" at 577,-858.49 h60
Top Paste:
  text ".Layer_Name" at 577,-858.49 h60
Bottom Paste:
  text ".Layer_Name" at 577,-858.49 h60
Top Solder:
  text ".Layer_Name" at 577,-858.49 h60
  text ".Layer_Name" at 577,-858.49 h60
Bottom Solder:
  text ".Layer_Name" at 577,-858.49 h60
Drill Guide:
  text ".Layer_Name" at 577,-858.49 h60
M1 Board Outline:
  the board outline again, w10
  text ".Layer_Name" at 577,-858.49 h60
M2 Board Dimensions:
  rectangle: 125,-400 500,-275
  rectangle: 0,-275 125,-150
  lines w7: 0,-275 1000,-275 ; 125,-400 125,-150 ; 250,-400 250,-150 ; 500,-400 500,-150 ; 750,-400 750,-150 ; 0,-400 0,-150 1000,-150 1000,-400 0,-400
  text ".Layer_Name" at 577,-858.49 h60
M3 3D STEP Top:
  text ".Layer_Name" at 577,-858.49 h60
M4 3D STEP Bottom:
  text ".Layer_Name" at 577,-858.49 h60
M5 Assembly Top:
  lines w10: -292,-930.17 6308,-930.17 ; -292,-726.83 6310,-726.83 ; -292,-523.5 -292,-1133.5 3713,-1133.5 6310,-1133.5 6310,-523.5 -291.5,-523.5 -291.5,-1133.5 1284,-1133.5 ; 2173,-1133.5 2173,-523.5 ; 3440,-726.83 3440,-523.5 ; 4280,-726.83 4280,-523.5 ; 4902,-1140 4902,-937.17
  text "COMPONENTS MARKED 'DNP' SHOULD NOT BE POPULATED." at 1153.5,-318.5 h60
  text "ASSEMBLY VARIANT:" at 1153,-434 h60
  text ".VariantName" at 2189,-434 h60
  text "PCB VIEWED FROM TOP SIDE" at -228.5,-655.67 h60
  text "BOARD #:" at 2248,-655.67 h60
  text ".PRJ_Number" at 2793.5,-655.67 h60
  text "REV:" at 3638,-655.67 h60
  text ".PCB_Rev" at 3929.5,-655.67 h60
  text "SVN REV:" at 4476,-655.67 h60
  text ".VersionControl_RevNumber" at 4982,-655.67 h60
  text "TID #:" at 2248,-859 h60
  text ".TID" at 2793.5,-859 h60
  text "PLOT NAME =" at -228.5,-1064.34 h60
  text ".plot_File_Name" at 577,-1064.34 h60
  text "GENERATED    :" at 2250,-1064.34 h60
  text ".Print_Date" at 3119.5,-1064.34 h60
  text ".Print_Time" at 3848.5,-1064.34 h60
  text "TEXAS INSTRUMENTS" at 5113,-1064.34 h60
M6 Assembly Bottom:
  lines w10: -292.5,-727.33 6309.5,-727.33 ; -290.5,-930.67 6309.5,-930.67 ; 1115.5,-1140.5 1115.5,-937.67 ; 1737.5,-727.33 1737.5,-524 ; 2577.5,-727.33 2577.5,-524 ; 3844.5,-1134 3844.5,-524 ; 4733.5,-1134 6309,-1134 6309,-524 -292.5,-524 -292.5,-1134 2304.5,-1134 6309.5,-1134 6309.5,-524
  text "COMPONENTS MARKED 'DNP' SHOULD NOT BE POPULATED." at 6102,-318 h60
  text ".VariantName" at 5058,-434 h60
  text "ASSEMBLY VARIANT:" at 6097,-434 h60
  text ".VersionControl_RevNumber" at 1035.5,-656.17 h60
  text "SVN REV:" at 1541.5,-656.17 h60
  text ".PCB_Rev" at 2088,-656.17 h60
  text "REV:" at 2379.5,-656.17 h60
  text ".PRJ_Number" at 3224,-656.17 h60
  text "BOARD #:" at 3769.5,-656.17 h60
  text "PCB VIEWED FROM BOTTOM SIDE" at 6246,-656.17 h60
  text ".TID" at 3224,-859.5 h60
  text "TID #:" at 3769.5,-859.5 h60
  text "TEXAS INSTRUMENTS" at 904.5,-1064.84 h60
  text ".Print_Time" at 2169,-1064.84 h60
  text ".Print_Date" at 2898,-1064.84 h60
  text "GENERATED    :" at 3767.5,-1064.84 h60
  text ".plot_File_Name" at 5440.5,-1064.84 h60
  text "PLOT NAME =" at 6246,-1064.84 h60
M9 Title Sheet:
  drawing of 57 lines, arcs and shapes, not listed
  text "1" at 739.84,8036.5 h70
  text "2" at 3235.5,8036.5 h70
  text "3" at 5724.84,8036.5 h70
  text "4" at 8231.51,8036.5 h70
  text "5" at 10730.5,8036.5 h70
  text "6" at 13235.5,8036.5 h70
  text "A" at -416.5,6893.5 h70
  text "A" at 14383.5,6893.5 h70
  text "B" at -416.5,4513.5 h70
  text "B" at 14383.5,4513.5 h70
  text "C" at -416.5,2138.5 h70
  text "C" at 14383.5,2138.5 h70
  text "PROJECT TITLE:" at 11343.5,277.5 h45
  text ".PRJ_Title" at 11393.5,144.17 h70
  text "DESIGNED FOR:" at 11343.5,-23.5 h45
  text ".PRJ_Customer" at 11393.5,-163.5 h70
  text "D" at -416.5,-231.5 h70
  text "D" at 14383.5,-231.5 h70
  text "FILE NAME:" at 11343.5,-323.5 h45
  text ".PCB_File_Name_No_Path" at 11393.5,-443.5 h70
  text "Texas Instruments (TI) and/or its licensors do not warrant the accuracy or completeness of this specification" at 6374,-605.34 h45
  text "ENGINEER:" at 11343.5,-613.5 h45
  text "LAYOUT BY:" at 12848.5,-613.5 h45
  text "or any information contained therein. TI and/or its licensors do not warrant that this design will meet" at 6329.01,-718 h45
  text ".PRJ_Engineer" at 11393.5,-768.49 h70
  text ".PCB_Layout" at 12899,-768.49 h70
  text "the specifications, will be suitable for your application or fit for any particular purpose, or will operate in" at 6329.01,-830.67 h45
  text ".Layer_Name" at 577,-858.49 h60
  text "ALTIUM DESIGNER VERSION:" at 12848.5,-923.5 h45
  text "an implementation. TI and/or its licensors do not warrant that the design is production worthy. You should" at 6329.01,-943.33 h45
  text "completely validate and test your design implementation to confirm the system functionality for your application." at 6374,-1056 h45
  text ".print_Scale" at 11393.5,-1056.83 h70
  text ".Application_BuildNumber" at 12899,-1056.83 h70
  text "1" at 739.84,-1263.5 h70
  text "2" at 3235.5,-1263.5 h70
  text "3" at 5724.84,-1263.5 h70
  text "4" at 8231.51,-1263.5 h70
  text "5" at 10730.5,-1263.5 h70
  text "6" at 13235.5,-1263.5 h70
M10 Fab Notes:
  drawing of 173 lines, arcs and shapes, not listed
  text "DESIGN INFORMATION" at 12377.02,6201 h60
  text "MIN. TRACK WIDTH:" at 11732.46,6021 h60
  text "8" at 12828.7,6021 h60
  text "MIL" at 12983.46,6021 h60
  text "MIN. CLEARANCE:" at 11732.46,5889 h60
  text "0.2" at 12768.7,5889 h60
  text "mm" at 12983.46,5889 h60
  text "MIN. VIA PAD SIZE:" at 11732.46,5757 h60
  text "22" at 12798.71,5757 h60
  text "MIL" at 12983.46,5757 h60
  text "0.05mm (2MIL)" at 12427.46,5615.29 h60
  text "MINIMUM ANNULAR RING" at 11403.23,5611 h60
  text "EXTERNAL" at 13135.46,5611 h60
  text "PER" at 11603.23,5493 h60
  text "IPC-D-275 CLASS 2 LEVEL C" at 11823.23,5493 h60
  text "MIL, HOLES" at 13311.46,5380.71 h60
  text "+/-" at 12919,5380 h60
  text "+/-" at 13773,5380 h60
  text "REGISTRATION TOLERANCES:" at 11403.23,5375 h60
  text "METAL" at 12603,5375 h60
  text "5" at 13179.2,5375 h60
  text "3" at 14012.2,5375 h60
  text "MIL" at 14128.46,5375 h60
  text "+/-" at 13773,5262 h60
  text "HOLE SIZE TOLERANCE (UNLESS OTHERWISE SPECIFIED):" at 11403.23,5257 h60
  text "3" at 14012.2,5257 h60
  text "MIL" at 14128.46,5257 h60
  text "MATERIAL:" at 11328.46,5047.54 h60
  text "FR-4 High Tg" at 12314.9,4907.21 h60
  text "FR-408" at 11749.46,4898.64 h60
  text "OTHER" at 13237.46,4898.64 h60
  text "X" at 12160,4895 h60
  text "62 MIL (1.6mm) +/-10%" at 12069.56,4735.92 h60
  text "THICKNESS:" at 11403.23,4731.64 h60
  text "X" at 11941.4,4731.64 h60
  text "OTHER" at 13354.46,4731.64 h60
  text "TOLERANCE:" at 11403.23,4573.64 h60
  text "X" at 12242.53,4573.64 h60
  text "ANSI IPC-6012 TYPE 3 CLASS 2" at 12429.48,4573.64 h60
  text "OTHER +/-" at 12429.46,4417.64 h60
  text "BOW & TWIST:" at 11403.23,4260.64 h60
  text "X" at 12242.53,4260.64 h60
  text "ANSI IPC-6012 TYPE 3 CLASS 2" at 12429.48,4260.64 h60
  text "OTHER +/-" at 12429.46,4102.13 h60
  text "DRILLING:" at 11328.46,3963.64 h60
  text "REFERENCE:" at 11403.23,3846.64 h60
  text "X" at 12051.46,3846.64 h60
  text "AS SHOWN" at 12238.46,3846.64 h60
  text "X" at 12952.46,3846.64 h60
  text "NC_DRILL FILES" at 13089.46,3846.64 h60
  text "PTH COPPER THICKNESS:" at 11403.23,3688.64 h60
  text "X" at 12533.46,3688.64 h60
  text "20-30 um" at 12670.46,3688.64 h60
  text "OTHER" at 13387.46,3688.64 h60
  text "BOARD FINISH:" at 11328.46,3529.64 h60
  text "SILKSCREEN:" at 11483.68,3411.64 h60
  text "X" at 12432.46,3411.64 h60
  text "TOP" at 12558.46,3411.64 h60
  text "X" at 12942.46,3411.64 h60
  text "BOTTOM" at 13069.46,3411.64 h60
  text "SILKSCREEN COLOR:" at 11483.68,3244.64 h60
  text "X" at 12431.42,3244.64 h60
  text "WHITE" at 12558.46,3244.64 h60
  text "OTHER" at 13069.46,3244.64 h60
  text "X" at 12562.42,3085.44 h60
  text "GREEN" at 12689.46,3085.44 h60
  text "OTHER" at 13307.46,3085.44 h60
  text "SOLDER RESIST COLOR:" at 11483.68,3074.64 h60
  text "X" at 12562.42,2915.44 h60
  text "MATTE" at 12689.46,2915.44 h60
  text "SEMI-GLOSS" at 13307,2914.8 h60
  text "IMMERSION GOLD (ENIG)" at 12389.46,2726.92 h60
  text "ENEPIG" at 13727,2723.64 h60
  text "SURFACE FINISH:" at 11328.46,2722.64 h60
  text "X" at 12202.51,2722.64 h60
  text "IMM. TIN/SILVER OR EQUIV" at 11658,2565.64 h60
  text "OTHER" at 13089.46,2565.64 h60
  text "X" at 12200,2390 h60
  text "ARRAY/PANEL:" at 11328.46,2386.64 h60
  text "CUT AND TRIM PER M1 BOARD OUTLINE" at 12389.46,2382.35 h60
  text "N.C. ROUTE" at 12389.46,2230.64 h60
  text "V. SCORE" at 13255.46,2230.64 h60
  text "CERTIFICATION:" at 11328.46,2093.64 h60
  text "MATERIALS AND WORKMANSHIP FOR ALL PCBS" at 12053.46,2093.64 h60
  text "TO MEET OR EXCEED THE REQUIREMENTS OF:" at 12053.46,1995.64 h60
  text "X" at 11679.96,1859.13 h60
  text "ANSI IPC-A-600F CLASS ->" at 11818.96,1859.13 h60
  text "X" at 13458.02,1859.13 h60
  text "2" at 13576.96,1859.14 h60
  text "1" at 13261.96,1857.64 h60
  text "3" at 13930.96,1857.64 h60
  text "X" at 12494.02,1699.64 h60
  text "RoHS" at 12630.96,1699.64 h60
  text "OTHER" at 13275.36,1699.64 h60
  text "PER ORDER" at 13672.42,1699.64 h60
  text "ALL BOARDS MUST MEET OR EXCEED UL94-V0 REQUIREMENTS." at 11356,1534 h60
  text "PCB MUST BEAR THE UL94V-0 UL REGISTERED MATERIAL ID NUMBER" at 11356,1414 h60
  text "ADDITIONAL REQUIREMENTS:" at 11328.46,1240.64 h60
  text "MICROSECTION:" at 11403.23,1125.64 h60
  text "YES" at 12308.96,1125.64 h60
  text "X" at 13640,970 h60
  text "REQUIRED" at 13170.46,969.49 h60
  text "BARE BOARD ELEC. TEST:" at 11403.23,966.64 h60
  text "NONE" at 12708.96,966.64 h60
  text "PER ORDER" at 13762.46,966.64 h60
  text ".Layer_Name" at 577,-858.49 h60
M11 Gerber Information:
  lines w10: -292,-930.17 6308,-930.17 ; -292,-726.83 6310,-726.83 ; -292,-523.5 -292,-1133.5 3713,-1133.5 6310,-1133.5 6310,-523.5 -291.5,-523.5 -291.5,-1133.5 1284,-1133.5 ; 2173,-1133.5 2173,-523.5 ; 3440,-726.83 3440,-523.5 ; 4280,-726.83 4280,-523.5 ; 4902,-1140 4902,-937.17
  text "ALL ARTWORK VIEWED FROM TOP SIDE" at -228.5,-655.67 h60
  text "BOARD #:" at 2248,-655.67 h60
  text ".PRJ_Number" at 2793.5,-655.67 h60
  text "REV:" at 3638,-655.67 h60
  text ".PCB_Rev" at 3929.5,-655.67 h60
  text "SVN REV:" at 4476,-655.67 h60
  text ".VersionControl_RevNumber" at 4982,-655.67 h60
  text "LAYER NAME =" at -228.5,-858.49 h60
  text "TID #:" at 2248,-859 h60
  text ".TID" at 2793.5,-859 h60
  text "PLOT NAME =" at -228.5,-1064.34 h60
  text ".plot_File_Name" at 577,-1064.34 h60
  text "GENERATED    :" at 2250,-1064.34 h60
  text ".Print_Date" at 3119.5,-1064.34 h60
  text ".Print_Time" at 3848.5,-1064.34 h60
  text "TEXAS INSTRUMENTS" at 5113,-1064.34 h60
M12 Stackup:
  drawing of 295 lines, arcs and shapes, not listed
  text "Layer" at 9790.58,7830 h60
  text "Name" at 10200.49,7830 h60
  text "Material" at 11130.23,7830 h60
  text "Thickness" at 11990,7830 h60
  text "Constant" at 12639.84,7830 h60
  text "Board Layer Stack" at 13209.7,7830 h60
  text "1" at 9790.58,7710 h60
  text "Top Overlay" at 10200.49,7710 h60
  text "2" at 9790.58,7590 h60
  text "Top Solder" at 10200.49,7590 h60
  text "Solder Resist" at 11130.23,7590 h60
  text "0.40mil" at 11990,7590 h60
  text "3.5" at 12639.84,7590 h60
  text "3" at 9790.58,7470 h60
  text "Top Layer" at 10200.49,7470 h60
  text "Copper" at 11130.23,7470 h60
  text "2.80mil" at 11990,7470 h60
  text "4" at 9790.58,7350 h60
  text "Dielectric1" at 10200.49,7350 h60
  text "FR-4" at 11130.23,7350 h60
  text "12.00mil" at 11990,7350 h60
  text "4.2" at 12639.84,7350 h60
  text "5" at 9790.58,7230 h60
  text "Mid-Layer 1" at 10200.49,7230 h60
  text "Copper" at 11130.23,7230 h60
  text "2.80mil" at 11990,7230 h60
  text "6" at 9790.58,7110 h60
  text "Dielectric3" at 10200.49,7110 h60
  text "FR-4" at 11130.23,7110 h60
  text "26.00mil" at 11990,7110 h60
  text "4.2" at 12639.84,7110 h60
  text "7" at 9790.58,6990 h60
  text "Mid-Layer 2" at 10200.49,6990 h60
  text "Copper" at 11130.23,6990 h60
  text "2.80mil" at 11990,6990 h60
  text "8" at 9790.58,6870 h60
  text "Dielectric2" at 10200.49,6870 h60
  text "FR-4" at 11130.23,6870 h60
  text "12.00mil" at 11990,6870 h60
  text "4.2" at 12639.84,6870 h60
  text "9" at 9790.58,6750 h60
  text "Bottom Layer" at 10200.49,6750 h60
  text "Copper" at 11130.23,6750 h60
  text "2.80mil" at 11990,6750 h60
  text "10" at 9790.58,6630 h60
  text "Bottom Solder" at 10200.49,6630 h60
  text "Solder Resist" at 11130.23,6630 h60
  text "0.40mil" at 11990,6630 h60
  text "3.5" at 12639.84,6630 h60
  text "11" at 9790.58,6510 h60
  text "Bottom Overlay" at 10200.49,6510 h60
  text ".Layer_Name" at 577,-858.49 h60
M13 Component Bodies Top:
  text ".Layer_Name" at 577,-858.49 h60
M14 Component Bodies Bottom:
  text ".Layer_Name" at 577,-858.49 h60
M15 Courtyards Top:
  text ".Layer_Name" at 577,-858.49 h60
M16 Courtyards Bottom:
  text ".Layer_Name" at 577,-858.49 h60
Drill Drawing:
  text ".Layer_Name" at 577,-858.49 h60

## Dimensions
0,-400 to 1000,-400 on M2 Board Dimensions
0,0 to 3000,0 on M2 Board Dimensions
0,0 to 0,2000 on M2 Board Dimensions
